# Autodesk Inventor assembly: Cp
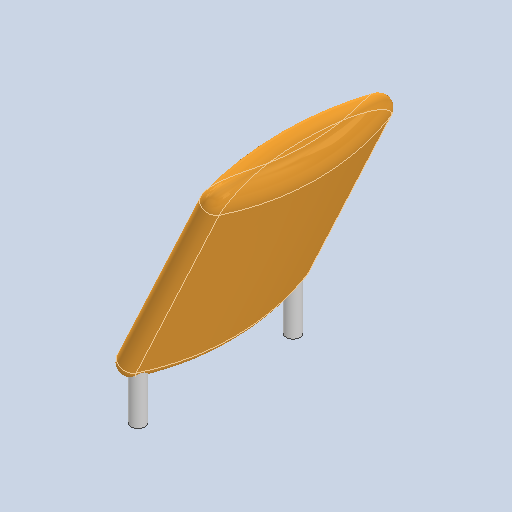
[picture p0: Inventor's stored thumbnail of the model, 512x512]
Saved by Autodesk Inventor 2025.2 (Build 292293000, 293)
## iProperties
Created: 2025-04
Part Number: Cp
Description: PART--DESC
Document SubType Name: Assembly
Designer: BennF
Author: BennF
Revision Number: NONE
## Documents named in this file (3)
- C:\Users\BennF\Nextcloud\Benutzer\CNC JarBeRi\existing parts\Electronics\RepRap A4988 Shied (USE WITHOUT ARDUINO)\reprap-a4988-1.snapshot.1\RepRap\RepRap\Cp.iam
- C:\Users\BennF\Nextcloud\Benutzer\CNC JarBeRi\existing parts\Electronics\RepRap A4988 Shied (USE WITHOUT ARDUINO)\reprap-a4988-1.snapshot.1\RepRap\RepRap\Cp Geometry.ipt
- C:\Users\BennF\Nextcloud\Benutzer\CNC JarBeRi\existing parts\Electronics\RepRap A4988 Shied (USE WITHOUT ARDUINO)\reprap-a4988-1.snapshot.1\RepRap\RepRap\pin16.ipt
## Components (2 placed, 2 different names)
1. Cp Geometry
2. pin16
